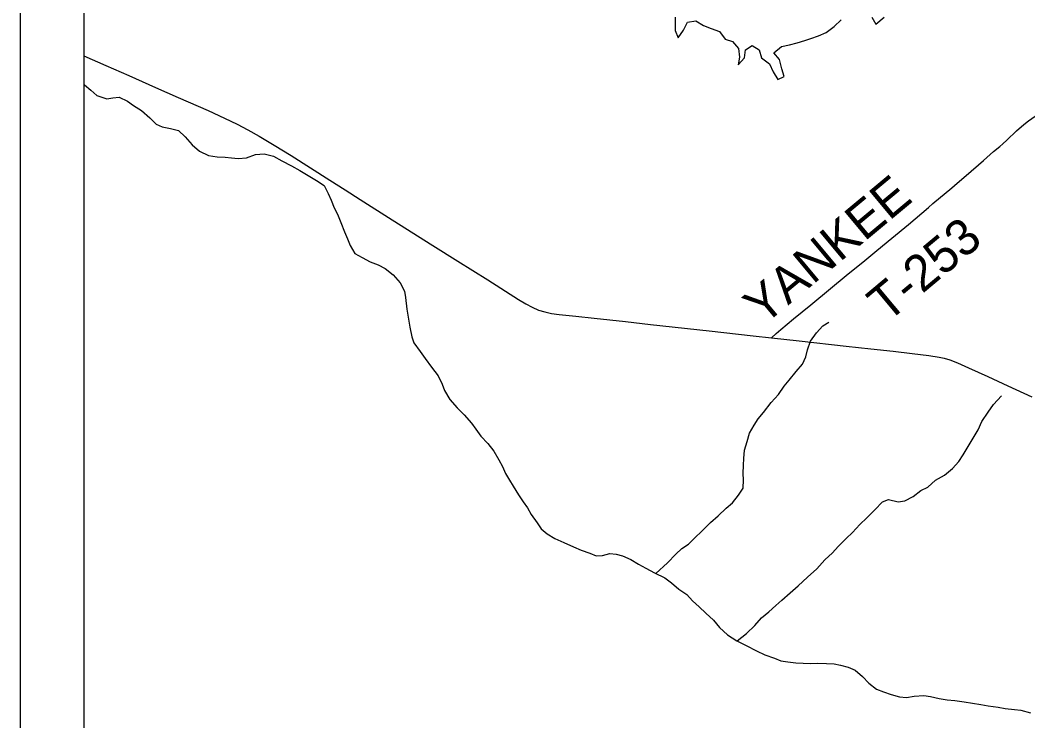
# Model space of a CAD drawing. Extents: x 0 to 34, y 0 to 22.
# Drawn here: x 2 to 3.583, y 17.368 to 18.468 of the extents above; entities that cross this region are included whole.
import ezdxf

# ---------------------------------------------------------------- set-up
doc = ezdxf.new("R2010")
doc.units = 0
for name, color, linetype in [('GM_X_Major_Lake', 7, 'Continuous'), ('GM_X_Minor_River', 7, 'Continuous'), ('GM_X_State_Route', 7, 'Continuous'), ('GM_X_Township_Road', 7, 'Continuous'), ('GM_X_Township_Road_Text', 7, 'Continuous'), ('SH_Data', 7, 'Continuous')]:
    doc.layers.add(name, color=color, linetype=linetype)

msp = doc.modelspace()

# ---------------------------------------------------------------- linework, layer by layer
at = {"layer": 'GM_X_Major_Lake'}
for points in [[(3.029, 18.4729), (3.0287, 18.4626), (3.0288, 18.4524), (3.0334, 18.4405), (3.0421, 18.4528), (3.0481, 18.4651), (3.0611, 18.4674), (3.0733, 18.4599), (3.0853, 18.4554), (3.0985, 18.4508), (3.1076, 18.4384), (3.1192, 18.4351), (3.1284, 18.4238), (3.1299, 18.4105), (3.128, 18.3984), (3.1378, 18.4091), (3.1393, 18.422), (3.1501, 18.4289), (3.1609, 18.4218), (3.1643, 18.4092), (3.1773, 18.3997), (3.183, 18.3874), (3.1902, 18.3751), (3.2002, 18.3797), (3.1964, 18.392), (3.193, 18.4065), (3.1839, 18.417), (3.1959, 18.4269), (3.2085, 18.4299), (3.2207, 18.433), (3.2325, 18.4365), (3.2421, 18.4396), (3.254, 18.4439), (3.2662, 18.4492), (3.2786, 18.4584), (3.2899, 18.469)], [(3.3378, 18.4734), (3.3439, 18.4622), (3.3574, 18.4729)]]:
    msp.add_lwpolyline(points, dxfattribs=at)
at = {"layer": 'GM_X_Minor_River'}
for points in [[(2.1, 18.3677), (2.1011, 18.3667), (2.1108, 18.3585), (2.1204, 18.35), (2.1362, 18.3447), (2.1457, 18.3464), (2.1556, 18.3474), (2.1684, 18.3411), (2.1781, 18.3344), (2.1904, 18.3266), (2.2038, 18.3149), (2.2135, 18.3053), (2.2232, 18.3009), (2.2364, 18.298), (2.2489, 18.2951), (2.2593, 18.2854), (2.27, 18.2727), (2.2819, 18.2629)], [(2.2819, 18.2629), (2.2958, 18.2558), (2.3094, 18.254), (2.3219, 18.2534), (2.3321, 18.2521), (2.3427, 18.2511), (2.3556, 18.252), (2.3697, 18.2574), (2.3834, 18.2587), (2.3981, 18.2546), (2.4112, 18.2475), (2.4262, 18.2396), (2.4393, 18.2325), (2.4524, 18.2243), (2.4655, 18.2164), (2.4774, 18.2086), (2.484, 18.1963), (2.4883, 18.1856), (2.4934, 18.1738), (2.4985, 18.1638), (2.5035, 18.1504), (2.5097, 18.1359), (2.5144, 18.1248), (2.5183, 18.1145), (2.5256, 18.1018), (2.5372, 18.0955), (2.5496, 18.0888), (2.5624, 18.084), (2.5736, 18.0785), (2.5859, 18.0684), (2.5967, 18.0556), (2.6036, 18.0426), (2.6053, 18.0327), (2.6076, 18.0143)], [(2.6076, 18.0143), (2.6103, 17.9954), (2.6121, 17.9859), (2.6153, 17.971), (2.6186, 17.9615), (2.6282, 17.9481), (2.636, 17.937), (2.6464, 17.9235), (2.6565, 17.9097), (2.6631, 17.8964), (2.6668, 17.8868), (2.6749, 17.8723), (2.6865, 17.8592), (2.6977, 17.8484), (2.7092, 17.8354), (2.7159, 17.8258), (2.7234, 17.8151), (2.7346, 17.8035), (2.7439, 17.7916), (2.752, 17.7775), (2.7579, 17.7675), (2.7623, 17.7564), (2.7686, 17.7457), (2.7742, 17.7362), (2.7827, 17.7228), (2.7901, 17.712), (2.7968, 17.7024), (2.8027, 17.6921), (2.812, 17.6787), (2.8183, 17.6691), (2.828, 17.6614), (2.8401, 17.654), (2.854, 17.6481), (2.8691, 17.6411), (2.8811, 17.636), (2.8947, 17.6309), (2.9049, 17.6269), (2.9148, 17.6272), (2.9262, 17.6308), (2.936, 17.6296), (2.9462, 17.6271), (2.959, 17.6213), (2.9714, 17.6139), (2.9827, 17.6073), (2.9963, 17.6003), (3.0125, 17.5925), (3.023, 17.5847), (3.0346, 17.5747), (3.0473, 17.5662), (3.0563, 17.5562), (3.0668, 17.5469), (3.0772, 17.5369), (3.0892, 17.5257), (3.0985, 17.5142), (3.1109, 17.503), (3.1259, 17.4933), (3.1406, 17.4863), (3.1564, 17.4777), (3.1696, 17.4715), (3.1847, 17.466), (3.1948, 17.462), (3.2058, 17.4604), (3.2187, 17.4587), (3.2297, 17.4581), (3.2418, 17.4576), (3.2524, 17.4582), (3.2664, 17.458), (3.2786, 17.4571), (3.2884, 17.4551), (3.3009, 17.4519), (3.3118, 17.4471), (3.3234, 17.4375), (3.3331, 17.4271), (3.3451, 17.4175), (3.356, 17.4131), (3.3681, 17.4092), (3.3813, 17.4052), (3.3923, 17.4043), (3.4041, 17.4064), (3.4197, 17.4077), (3.4302, 17.4061), (3.4438, 17.4028), (3.4563, 17.4008), (3.4681, 17.3995), (3.4828, 17.3977), (3.4957, 17.3953), (3.5089, 17.3932), (3.5206, 17.3912), (3.5365, 17.389), (3.5471, 17.387), (3.5619, 17.3853), (3.5721, 17.3844), (3.5868, 17.3804)], [(2.9984, 17.5993), (3.0166, 17.6159), (3.0297, 17.6294), (3.0393, 17.6384), (3.05, 17.6455), (3.0604, 17.6556), (3.0704, 17.6649), (3.0842, 17.6792), (3.0965, 17.6896), (3.1092, 17.7016), (3.1188, 17.7102), (3.1285, 17.7222), (3.1355, 17.7331), (3.1364, 17.7464), (3.1358, 17.7563), (3.1364, 17.7696), (3.1369, 17.7798), (3.1378, 17.7931), (3.1418, 17.8067), (3.1458, 17.8196), (3.1528, 17.832), (3.1594, 17.8421), (3.1675, 17.8523), (3.1799, 17.8677), (3.1914, 17.8804), (3.2, 17.8932), (3.2081, 17.903), (3.2189, 17.9165), (3.2289, 17.9281), (3.2344, 17.9394), (3.2368, 17.9504), (3.2416, 17.9644), (3.2509, 17.9772), (3.2609, 17.9884), (3.2704, 17.994)], [(3.1263, 17.4932), (3.1412, 17.5049), (3.1539, 17.5176), (3.1643, 17.5296), (3.1759, 17.539), (3.187, 17.5491), (3.1966, 17.5573), (3.2097, 17.5689), (3.2223, 17.5797), (3.2366, 17.5936), (3.2515, 17.6067), (3.2639, 17.6205), (3.2762, 17.6314), (3.2847, 17.6415), (3.2977, 17.6542), (3.3077, 17.6636), (3.3189, 17.676), (3.3301, 17.6868), (3.3424, 17.6992), (3.3547, 17.7119), (3.3642, 17.7152), (3.379, 17.712), (3.3896, 17.7133), (3.403, 17.72), (3.4148, 17.7293), (3.4259, 17.7349), (3.4378, 17.7457), (3.452, 17.7539), (3.4643, 17.7643), (3.4747, 17.7752), (3.4813, 17.7854), (3.489, 17.7989), (3.4968, 17.8117), (3.505, 17.8249), (3.5108, 17.8381), (3.5205, 17.8528), (3.5291, 17.8648), (3.5414, 17.8783)]]:
    msp.add_lwpolyline(points, dxfattribs=at)
at = {"layer": 'GM_X_State_Route'}
msp.add_lwpolyline([(2.1, 18.4126), (2.1348, 18.3971), (2.1706, 18.3813), (2.2127, 18.3627), (2.2484, 18.3467), (2.2951, 18.3263), (2.3212, 18.3146), (2.3408, 18.3052), (2.3579, 18.2962), (2.3752, 18.2864), (2.3992, 18.272), (2.4257, 18.2558), (2.4865, 18.217), (2.5106, 18.2017), (2.5343, 18.1868), (2.5846, 18.1547), (2.6481, 18.1145), (2.6876, 18.0898), (2.7344, 18.0603), (2.7826, 18.0295), (2.7943, 18.0226), (2.8041, 18.0174), (2.8144, 18.0131), (2.8244, 18.01), (2.8346, 18.0078), (2.8468, 18.0059), (2.8728, 18.0032), (2.9018, 18.0002), (2.9507, 17.9948), (2.9902, 17.9905), (3.0822, 17.9805), (3.1514, 17.9727), (3.18, 17.9695), (3.2236, 17.9647), (3.2977, 17.9565), (3.336, 17.9523), (3.3712, 17.9482), (3.4014, 17.9447), (3.4273, 17.9416), (3.4434, 17.9392), (3.4513, 17.9375), (3.4603, 17.9347), (3.4725, 17.93), (3.4896, 17.9225), (3.5201, 17.9084), (3.5517, 17.894), (3.5889, 17.8766)], dxfattribs=at)
at = {"layer": 'GM_X_Township_Road'}
for points in [[(3.7787, 17.0143), (3.7921, 17.074), (3.9903, 17.6899), (4.0744, 17.9948), (4.1901, 18.4135), (4.1943, 18.4289), (4.2897, 18.7747), (4.3389, 18.9527), (4.4789, 19.5742), (4.4849, 19.6021), (4.4654, 19.6041), (3.501, 19.6889), (3.4805, 19.8366), (3.1735, 19.8394), (3.1019, 19.912), (2.3144, 20.5665), (2.1, 20.7431), (2.1, 15.597), (2.2517, 15.5643), (3.1228, 15.3686), (3.3385, 15.3189), (3.6691, 16.5264), (3.7277, 16.7873)], [(3.4721, 18.2124), (3.486, 18.2243), (3.5131, 18.2481), (3.529, 18.262), (3.539, 18.2702), (3.5437, 18.2742), (3.55, 18.2801), (3.5652, 18.2944), (3.5766, 18.3047), (3.5839, 18.3104), (3.5945, 18.3177), (3.604, 18.3235), (3.6126, 18.3284), (3.6198, 18.332), (3.6271, 18.335), (3.6347, 18.3372), (3.6419, 18.3386), (3.6492, 18.3394), (3.6603, 18.34), (3.6808, 18.3402), (3.6894, 18.3402), (3.6938, 18.3401), (3.708, 18.3398), (3.7156, 18.3395)], [(3.4339, 18.1804), (3.4633, 18.2049), (3.4721, 18.2124)], [(3.18, 17.9695), (3.1875, 17.9762), (3.1949, 17.9827), (3.215, 17.9993), (3.2419, 18.0214), (3.3009, 18.0699), (3.3236, 18.0883), (3.3456, 18.1065), (3.369, 18.126), (3.3954, 18.1476), (3.4266, 18.1743), (3.4339, 18.1804)]]:
    msp.add_lwpolyline(points, dxfattribs=at)
at = {"layer": 'SH_Data'}
for p, q in [((2, 21), (2, 14)), ((2.1, 20.9), (2.1, 14.1))]:
    msp.add_line(p, q, dxfattribs=at)

# ---------------------------------------------------------------- texts
at = {"layer": 'GM_X_Township_Road_Text'}
for s, rotation, p in [('YANKEE', 39.8054, (3.1673, 17.9876)), ('T-253', 39.8409, (3.3619, 17.9921))]:
    msp.add_text(s, height=0.05682, rotation=rotation, dxfattribs=at).set_placement(p)

doc.saveas('drawing.dxf')
